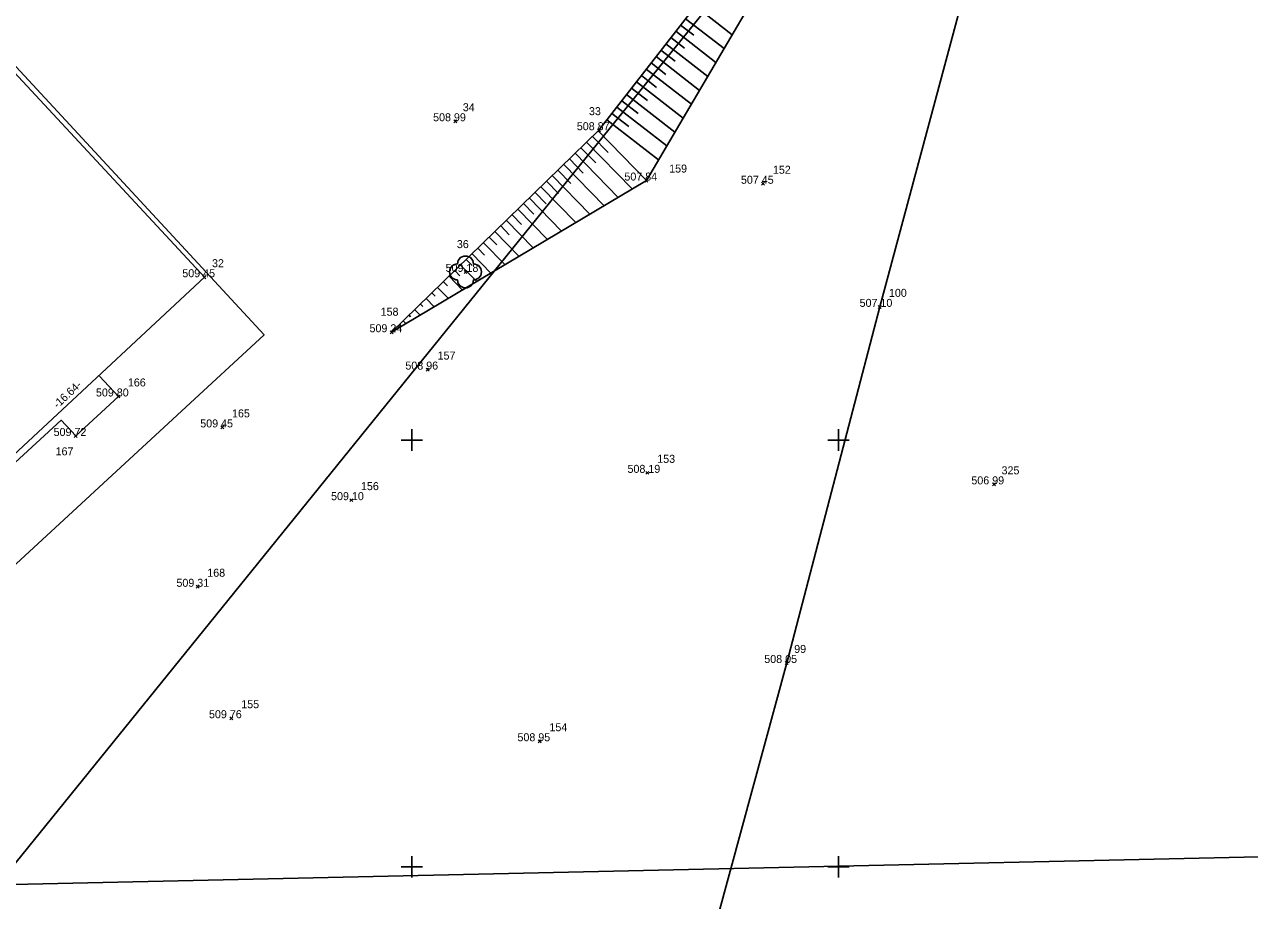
# Model space of a CAD drawing. Extents: x -408550 to -407654, y -1233019 to -1231230.
# Drawn here: x -407958.1 to -407900.7, y -1232101.6 to -1232060.5 of the extents above; entities that cross this region are included whole.
import ezdxf

# ---------------------------------------------------------------- set-up
doc = ezdxf.new("R2010")
doc.units = 0
for name, color, linetype in [('Level 1', 7, 'Continuous'), ('Level 11', 7, 'Continuous'), ('Level 12', 7, 'Continuous'), ('Level 13', 7, 'Continuous'), ('Level 16', 7, 'Continuous'), ('Level 23', 7, 'Continuous'), ('Level 26', 7, 'Continuous'), ('Level 28', 7, 'Continuous'), ('Level 4', 7, 'Continuous'), ('Level 40', 7, 'Continuous')]:
    doc.layers.add(name, color=color, linetype=linetype)

msp = doc.modelspace()

# ---------------------------------------------------------------- linework, layer by layer
at = {"layer": 'Level 1'}
for p, q in [((-407940, -1232079.5), (-407940, -1232080.5)), ((-407920, -1232079.5), (-407920, -1232080.5)), ((-407940.5, -1232080), (-407939.5, -1232080)), ((-407920.5, -1232080), (-407919.5, -1232080)), ((-407940, -1232099.5), (-407940, -1232100.5)), ((-407920, -1232099.5), (-407920, -1232100.5)), ((-407940.5, -1232100), (-407939.5, -1232100)), ((-407920.5, -1232100), (-407919.5, -1232100))]:
    msp.add_line(p, q, dxfattribs=at)
for points in [[(-407865.11, -1232098.76), (-407959.41, -1232100.85), (-407908.02, -1232037.31), (-407927.08, -1232021.88), (-407925.98, -1232020.38), (-407922.27, -1232015.79), (-407913.48, -1232004.91), (-407905.89, -1231995.51), (-407896.46, -1231983.85)], [(-407908.02, -1232037.31), (-407959.41, -1232100.85), (-407964.75, -1232098.99), (-407974.67, -1232095.53), (-407985.8, -1232091.65), (-408004.8, -1232085.03), (-408023.96, -1232078.34), (-408035.27, -1232074.4), (-408044.77, -1232071.09)], [(-408044.77, -1232071.09), (-408035.27, -1232074.4), (-408023.96, -1232078.34), (-408004.8, -1232085.03), (-407985.8, -1232091.65), (-407974.67, -1232095.53), (-407964.75, -1232098.99), (-407959.41, -1232100.85), (-407865.11, -1232098.76), (-407866.39, -1232098.97), (-407901.79, -1232106.39), (-407899.44, -1232117.51), (-407894.61, -1232140.35), (-407874.15, -1232135.48), (-407862.74, -1232131.55), (-407855.39, -1232125.61), (-407852.28, -1232122.69), (-407848.72, -1232121.07), (-407838.47, -1232120.5), (-407847.32, -1232123.67), (-407848.36, -1232134.5), (-407841.61, -1232145.17), (-407846.34, -1232175.35)]]:
    msp.add_lwpolyline(points, dxfattribs=at)
for points in [[(-407983.55, -1232015.52), (-407983.6, -1232014.52), (-407981.73, -1232014.41), (-407981.67, -1232015.42), (-407970.32, -1232014.9), (-407969.16, -1232040.17), (-407975.2, -1232040.45), (-407974.95, -1232045.12), (-407973.55, -1232045.08), (-407973.31, -1232049.36), (-407974.72, -1232049.44), (-407974.48, -1232053.95), (-407972.3, -1232056.28), (-407968.04, -1232052.23), (-407946.92, -1232075.07), (-407959.14, -1232086.36), (-407980.2, -1232063.57), (-407977.4, -1232060.97), (-407981.18, -1232056.94), (-407981.8, -1232045.69), (-407982.07, -1232040.75), (-407985.47, -1232040.9), (-407986.59, -1232015.66)], [(-407983.6, -1232014.52), (-407983.55, -1232015.52), (-407986.59, -1232015.66), (-407985.47, -1232040.9), (-407982.07, -1232040.75), (-407981.8, -1232045.69), (-407981.18, -1232056.94), (-407977.4, -1232060.97), (-407980.2, -1232063.57), (-407959.14, -1232086.36), (-407946.92, -1232075.07), (-407968.04, -1232052.23), (-407972.3, -1232056.28), (-407974.48, -1232053.95), (-407974.72, -1232049.44), (-407973.31, -1232049.36), (-407973.55, -1232045.08), (-407974.95, -1232045.12), (-407975.2, -1232040.45), (-407969.16, -1232040.17), (-407970.32, -1232014.9), (-407981.67, -1232015.42), (-407981.73, -1232014.41)]]:
    msp.add_lwpolyline(points, close=True, dxfattribs=at)
at = {"layer": 'Level 11'}
msp.add_lwpolyline([(-407989.46, -1232013.01), (-407973.21, -1232012.23), (-407971.98, -1232037.5), (-407977.95, -1232037.78), (-407977.733, -1232042.415), (-407976.39, -1232042.37), (-407976.14, -1232046.74), (-407977.45, -1232046.87), (-407977.009, -1232051.318), (-407974.962, -1232053.765), (-407970.82, -1232049.62), (-407949.71, -1232072.37), (-407961.89, -1232083.71), (-407983.01, -1232060.92), (-407980.3, -1232058.38), (-407984.06, -1232054.32), (-407985.01, -1232038.14), (-407988.32, -1232038.28)], close=True, dxfattribs=at)
at = {"layer": 'Level 12'}
msp.add_lwpolyline([(-408056.73, -1232038.31), (-408035.18, -1232049.43), (-408016.67, -1232058.98), (-407995.64, -1232070.23), (-407983.94, -1232082.87), (-407968.55, -1232099.65), (-407955.47, -1232103.17), (-407935.56, -1232108.32), (-407927.78, -1232110.15), (-407922.43, -1232090.45), (-407918.07, -1232073.76), (-407912.71, -1232053.79), (-407910.82, -1232047.19), (-407908.67, -1232042.13), (-407906.88, -1232038.31), (-407908.34, -1232037.12), (-407921.23, -1232026.55), (-407939.09, -1232011.64)], dxfattribs=at)
at = {"layer": 'Level 13'}
for p, q in [((-407926.71, -1232059.66), (-407924.98, -1232061.003)), ((-407927.4, -1232060.549), (-407926.786, -1232061.026)), ((-407927.17, -1232060.252), (-407925.364, -1232061.655)), ((-407927.86, -1232061.141), (-407927.22, -1232061.638)), ((-407927.63, -1232060.845), (-407925.747, -1232062.307)), ((-407928.32, -1232061.733), (-407927.655, -1232062.25)), ((-407928.09, -1232061.437), (-407926.13, -1232062.959)), ((-407928.78, -1232062.326), (-407928.089, -1232062.862)), ((-407928.55, -1232062.029), (-407926.514, -1232063.611)), ((-407929.24, -1232062.918), (-407928.524, -1232063.474)), ((-407929.01, -1232062.622), (-407926.897, -1232064.263)), ((-407929.7, -1232063.51), (-407928.958, -1232064.087)), ((-407929.47, -1232063.214), (-407927.28, -1232064.915)), ((-407930.16, -1232064.103), (-407929.393, -1232064.699)), ((-407929.93, -1232063.806), (-407927.664, -1232065.567)), ((-407930.62, -1232064.695), (-407929.827, -1232065.311)), ((-407930.39, -1232064.399), (-407928.047, -1232066.219)), ((-407930.85, -1232064.991), (-407928.43, -1232066.871)), ((-407931.535, -1232065.778), (-407930.801, -1232066.53)), ((-407931.267, -1232065.516), (-407929, -1232067.84)), ((-407932.072, -1232066.301), (-407931.38, -1232067.011)), ((-407931.804, -1232066.039), (-407929.663, -1232068.235)), ((-407932.609, -1232066.825), (-407931.959, -1232067.492)), ((-407932.341, -1232066.563), (-407930.325, -1232068.629)), ((-407933.414, -1232067.61), (-407931.651, -1232069.419)), ((-407933.146, -1232067.349), (-407932.538, -1232067.972)), ((-407932.878, -1232067.087), (-407930.988, -1232069.024)), ((-407933.951, -1232068.134), (-407932.314, -1232069.813)), ((-407933.683, -1232067.872), (-407933.117, -1232068.453)), ((-407934.488, -1232068.658), (-407932.976, -1232070.208)), ((-407934.22, -1232068.396), (-407933.695, -1232068.934)), ((-407935.025, -1232069.181), (-407933.639, -1232070.603)), ((-407934.757, -1232068.92), (-407934.274, -1232069.414)), ((-407935.562, -1232069.705), (-407934.302, -1232070.997)), ((-407935.294, -1232069.443), (-407934.853, -1232069.895)), ((-407936.368, -1232070.491), (-407936.011, -1232070.856)), ((-407936.099, -1232070.229), (-407934.965, -1232071.392)), ((-407935.831, -1232069.967), (-407935.432, -1232070.376)), ((-407936.904, -1232071.014), (-407936.59, -1232071.337)), ((-407936.636, -1232070.752), (-407935.627, -1232071.786)), ((-407937.441, -1232071.538), (-407937.168, -1232071.818)), ((-407937.173, -1232071.276), (-407936.29, -1232072.181)), ((-407937.978, -1232072.061), (-407937.747, -1232072.298)), ((-407937.71, -1232071.8), (-407936.953, -1232072.576)), ((-407938.515, -1232072.585), (-407938.326, -1232072.779)), ((-407938.247, -1232072.323), (-407937.616, -1232072.97)), ((-407939.321, -1232073.371), (-407938.941, -1232073.76)), ((-407939.052, -1232073.109), (-407938.905, -1232073.26)), ((-407938.784, -1232072.847), (-407938.278, -1232073.365)), ((-407939.858, -1232073.894), (-407939.604, -1232074.154)), ((-407939.589, -1232073.632), (-407939.484, -1232073.741)), ((-407940.394, -1232074.418), (-407940.267, -1232074.549)), ((-407940.126, -1232074.156), (-407940.062, -1232074.221)), ((-407940.931, -1232074.942), (-407940.929, -1232074.944)), ((-407940.663, -1232074.68), (-407940.641, -1232074.702))]:
    msp.add_line(p, q, dxfattribs=at)
msp.add_lwpolyline([(-407928.84, -1232043.94), (-407924.2, -1232040.27), (-407930.21, -1232048.56), (-407926.93, -1232054.36), (-407924.42, -1232060.05), (-407929, -1232067.84), (-407940.94, -1232074.95), (-407931.23, -1232065.48), (-407926.71, -1232059.66), (-407931.56, -1232056.03), (-407936.78, -1232051.12), (-407946.91, -1232042.39), (-407951.89, -1232037.1), (-407955.66, -1232033.43), (-407956.53, -1232029.14), (-407959.71, -1232027.29), (-407963.37, -1232025.1), (-407959.59, -1232025.56), (-407955.74, -1232027.26), (-407941.12, -1232039.53), (-407932.66, -1232049.18), (-407931.8, -1232047.55)], close=True, dxfattribs=at)
at = {"layer": 'Level 16'}
msp.add_lwpolyline([(-407983.01, -1232060.92), (-407983.22, -1232061.16), (-407961.92, -1232084.12), (-407956.419, -1232079.076), (-407955.74, -1232079.81), (-407953.74, -1232077.96), (-407954.623, -1232077.006)], dxfattribs=at)
at = {"layer": 'Level 23'}
for points in [[(-407937.891, -1232065.129), (-407938.029, -1232064.991)], [(-407938.029, -1232065.129), (-407937.891, -1232064.991)], [(-407931.161, -1232065.549), (-407931.299, -1232065.411)], [(-407931.299, -1232065.549), (-407931.161, -1232065.411)], [(-407928.931, -1232067.909), (-407929.069, -1232067.771)], [(-407929.069, -1232067.909), (-407928.931, -1232067.771)], [(-407923.471, -1232068.059), (-407923.609, -1232067.921)], [(-407923.609, -1232068.059), (-407923.471, -1232067.921)], [(-407937.411, -1232072.189), (-407937.549, -1232072.051)], [(-407937.549, -1232072.189), (-407937.411, -1232072.051)], [(-407949.641, -1232072.439), (-407949.779, -1232072.301)], [(-407949.779, -1232072.439), (-407949.641, -1232072.301)], [(-407918.001, -1232073.829), (-407918.139, -1232073.691)], [(-407918.139, -1232073.829), (-407918.001, -1232073.691)], [(-407940.871, -1232075.019), (-407941.009, -1232074.881)], [(-407941.009, -1232075.019), (-407940.871, -1232074.881)], [(-407939.181, -1232076.769), (-407939.319, -1232076.631)], [(-407939.319, -1232076.769), (-407939.181, -1232076.631)], [(-407953.671, -1232078.029), (-407953.809, -1232077.891)], [(-407953.809, -1232078.029), (-407953.671, -1232077.891)], [(-407948.801, -1232079.479), (-407948.939, -1232079.341)], [(-407948.939, -1232079.479), (-407948.801, -1232079.341)], [(-407955.671, -1232079.879), (-407955.809, -1232079.741)], [(-407955.809, -1232079.879), (-407955.671, -1232079.741)], [(-407928.891, -1232081.609), (-407929.029, -1232081.471)], [(-407929.029, -1232081.609), (-407928.891, -1232081.471)], [(-407912.651, -1232082.149), (-407912.789, -1232082.011)], [(-407912.789, -1232082.149), (-407912.651, -1232082.011)], [(-407942.761, -1232082.889), (-407942.899, -1232082.751)], [(-407942.899, -1232082.889), (-407942.761, -1232082.751)], [(-407949.961, -1232086.949), (-407950.099, -1232086.811)], [(-407950.099, -1232086.949), (-407949.961, -1232086.811)], [(-407922.361, -1232090.519), (-407922.499, -1232090.381)], [(-407922.499, -1232090.519), (-407922.361, -1232090.381)], [(-407948.381, -1232093.109), (-407948.519, -1232092.971)], [(-407948.519, -1232093.109), (-407948.381, -1232092.971)], [(-407933.941, -1232094.189), (-407934.079, -1232094.051)], [(-407934.079, -1232094.189), (-407933.941, -1232094.051)]]:
    msp.add_lwpolyline(points, dxfattribs=at)
at = {"layer": 'Level 28'}
msp.add_lwpolyline([(-407936.73, -1232072.12), (-407936.767, -1232072.283), (-407936.871, -1232072.413), (-407937.022, -1232072.486), (-407937.105, -1232072.495), (-407937.142, -1232072.658), (-407937.246, -1232072.788), (-407937.397, -1232072.861), (-407937.563, -1232072.861), (-407937.714, -1232072.788), (-407937.818, -1232072.658), (-407937.855, -1232072.495), (-407937.938, -1232072.486), (-407938.089, -1232072.413), (-407938.193, -1232072.283), (-407938.23, -1232072.12), (-407938.193, -1232071.957), (-407938.089, -1232071.827), (-407937.938, -1232071.754), (-407937.855, -1232071.745), (-407937.818, -1232071.582), (-407937.714, -1232071.452), (-407937.563, -1232071.379), (-407937.397, -1232071.379), (-407937.246, -1232071.452), (-407937.142, -1232071.582), (-407937.105, -1232071.745), (-407937.022, -1232071.754), (-407936.871, -1232071.827), (-407936.767, -1232071.957)], close=True, dxfattribs=at)
msp.add_lwpolyline([(-407937.499, -1232072.12), (-407937.48, -1232072.12), (-407937.461, -1232072.12)], dxfattribs=at)
at = {"layer": 'Level 4'}
msp.add_lwpolyline([(-407823.58, -1231999.5), (-407837.41, -1231987.92), (-407838.34, -1231987.97), (-407840.86, -1231988.11), (-407842.83, -1231990.51), (-407843.19, -1231994.63), (-407839.56, -1232019.93), (-407835.24, -1232048.6), (-407834.29, -1232054.76), (-407828.44, -1232092.63), (-407834.82, -1232093.74), (-407838.8, -1232094.4), (-407843.51, -1232095.18), (-407846.32, -1232095.65), (-407865.11, -1232098.76), (-407959.41, -1232100.85), (-407964.75, -1232098.99), (-407974.67, -1232095.53), (-407985.8, -1232091.65), (-408004.8, -1232085.03), (-408023.96, -1232078.34), (-408035.27, -1232074.4), (-408044.77, -1232071.09)], dxfattribs=at)

# ---------------------------------------------------------------- texts
at = {"layer": 'Level 1'}
msp.add_text('-16.64-', height=0.375, rotation=42.97183, dxfattribs=at).set_placement((-407956.595, -1232078.542))
at = {"layer": 'Level 26'}
for s, p in [('34', (-407937.606, -1232064.59)), ('33', (-407931.694, -1232064.774)), ('159', (-407927.937, -1232067.464)), ('152', (-407923.077, -1232067.52)), ('36', (-407937.884, -1232071.006)), ('32', (-407949.356, -1232071.9)), ('100', (-407917.64, -1232073.29)), ('158', (-407941.456, -1232074.175)), ('157', (-407938.787, -1232076.23)), ('166', (-407953.298, -1232077.49)), ('165', (-407948.418, -1232078.94)), ('167', (-407956.685, -1232080.719)), ('153', (-407928.497, -1232081.07)), ('325', (-407912.364, -1232081.61)), ('156', (-407942.378, -1232082.35)), ('168', (-407949.578, -1232086.41)), ('99', (-407922.079, -1232089.98)), ('155', (-407947.987, -1232092.57)), ('154', (-407933.547, -1232093.65))]:
    msp.add_text(s, height=0.375, dxfattribs=at).set_placement(p)
at = {"layer": 'Level 40'}
for s, p in [('508 99', (-407938.997, -1232065.06)), ('508 87', (-407932.264, -1232065.48)), ('507 84', (-407930.034, -1232067.84)), ('507 45', (-407924.574, -1232067.99)), ('509 45', (-407950.747, -1232072.37)), ('509 18', (-407938.411, -1232072.12)), ('507 10', (-407919.014, -1232073.76)), ('509 24', (-407941.977, -1232074.95)), ('508 96', (-407940.296, -1232076.7)), ('509 80', (-407954.793, -1232077.96)), ('509 45', (-407949.907, -1232079.41)), ('509 72', (-407956.777, -1232079.81)), ('508 19', (-407929.889, -1232081.54)), ('506 99', (-407913.778, -1232082.08)), ('509 10', (-407943.777, -1232082.82)), ('509 31', (-407951.023, -1232086.88)), ('508 05', (-407923.48, -1232090.45)), ('509 76', (-407949.497, -1232093.04)), ('508 95', (-407935.045, -1232094.12))]:
    msp.add_text(s, height=0.375, dxfattribs=at).set_placement(p)

doc.saveas('drawing.dxf')
